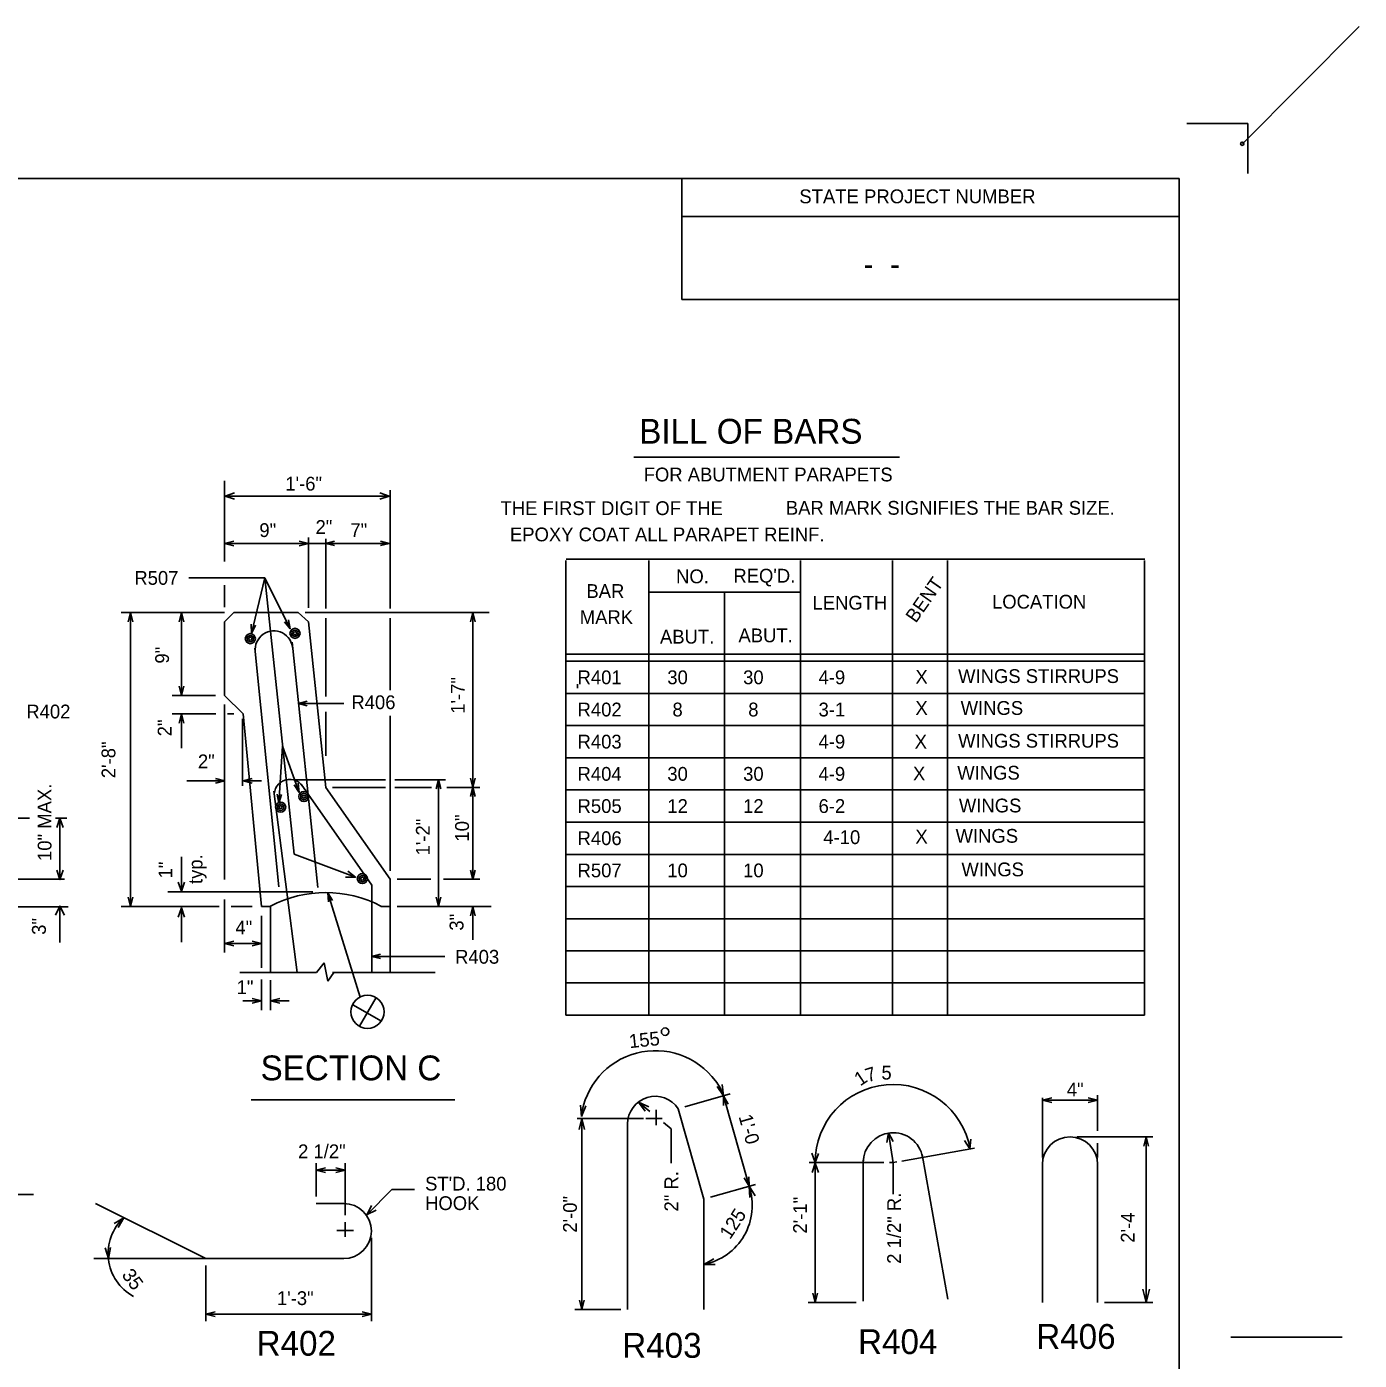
# Model space of a CAD drawing. Extents: x -3.6 to 32.6, y 15.5 to 40.2.
# Drawn here: x 20.52 to 32.6, y 27.56 to 39.65 of the extents above; entities that cross this region are included whole.
import ezdxf

# ---------------------------------------------------------------- set-up
doc = ezdxf.new("R2010")
doc.units = 0
for name, color, linetype in [('Level 1', 7, 'Continuous'), ('Level 2', 7, 'Continuous'), ('Level 37', 7, 'Continuous'), ('Level 49', 7, 'Continuous')]:
    doc.layers.add(name, color=color, linetype=linetype)

msp = doc.modelspace()

# ---------------------------------------------------------------- linework, layer by layer
at = {"layer": 'Level 1'}
for p, q in [((31.591, 38.772), (31.036, 38.772)), ((31.591, 38.317), (31.591, 38.772)), ((30.966, 38.272), (-0.41, 38.272)), ((26.46, 38.272), (26.46, 37.177)), ((30.966, 17.273), (30.966, 38.272)), ((26.46, 37.928), (30.966, 37.928)), ((26.46, 37.177), (30.966, 37.177))]:
    msp.add_line(p, q, dxfattribs=at)
at = {"layer": 'Level 2'}
for p, q in [((31.54, 38.588), (32.6, 39.649)), ((26.025, 35.748), (28.432, 35.748)), ((22.316, 35.006), (22.316, 35.532)), ((23.816, 35.018), (23.816, 35.447)), ((23.806, 35.394), (22.322, 35.394)), ((22.316, 35.006), (22.316, 34.802)), ((22.316, 34.965), (23.137, 34.965)), ((23.075, 34.381), (23.075, 35.018)), ((23.075, 34.687), (23.075, 34.965)), ((23.137, 34.965), (23.243, 34.965)), ((23.233, 34.375), (23.233, 35.006)), ((23.233, 34.965), (23.313, 34.985)), ((23.233, 34.965), (23.808, 34.965)), ((23.233, 34.965), (23.313, 34.945)), ((23.808, 34.965), (23.728, 34.985)), ((23.808, 34.965), (23.728, 34.945)), ((23.816, 34.375), (23.816, 35.018)), ((25.412, 34.822), (30.655, 34.822)), ((25.41, 34.81), (25.41, 30.689)), ((26.16, 34.81), (26.16, 30.689)), ((27.535, 34.81), (27.535, 30.689)), ((28.368, 34.81), (28.368, 30.689)), ((28.868, 34.81), (28.868, 30.689)), ((30.654, 34.81), (30.654, 30.689)), ((22.449, 34.653), (21.993, 34.653)), ((22.316, 34.387), (22.316, 34.586)), ((22.68, 34.653), (22.368, 34.653)), ((22.559, 34.15), (22.68, 34.653)), ((22.68, 34.653), (22.911, 34.19)), ((22.68, 34.653), (22.946, 32.149)), ((26.16, 34.522), (27.535, 34.522)), ((26.848, 34.522), (26.848, 30.689)), ((30.654, 34.522), (30.654, 30.689)), ((21.841, 34.338), (21.378, 34.338)), ((21.462, 31.674), (21.462, 34.338)), ((22.316, 34.338), (21.841, 34.338)), ((21.924, 33.588), (21.924, 34.338)), ((22.316, 34.254), (22.4, 34.338)), ((22.983, 34.338), (22.4, 34.338)), ((22.983, 34.338), (23.075, 34.255)), ((23.045, 34.338), (24.714, 34.338)), ((24.567, 32.754), (24.567, 34.338)), ((22.316, 34.254), (22.316, 33.588)), ((22.559, 34.15), (22.558, 34.232)), ((22.559, 34.15), (22.597, 34.223)), ((22.911, 34.19), (22.858, 34.253)), ((22.911, 34.19), (22.894, 34.271)), ((23.233, 32.754), (23.075, 34.255)), ((23.233, 33.577), (23.233, 34.289)), ((23.816, 33.635), (23.816, 34.289)), ((22.807, 31.853), (22.591, 34.016)), ((22.807, 31.853), (22.591, 34.016)), ((22.927, 34.07), (23.161, 31.847)), ((25.41, 33.96), (30.654, 33.96)), ((25.41, 33.897), (30.654, 33.897)), ((21.924, 33.755), (21.924, 33.588)), ((25.41, 33.606), (30.654, 33.606)), ((25.515, 33.689), (25.515, 33.654)), ((22.233, 33.588), (21.841, 33.588)), ((22.15, 33.588), (21.841, 33.588)), ((22.316, 33.588), (22.483, 33.421)), ((22.316, 33.504), (22.316, 31.919)), ((22.985, 33.514), (23.065, 33.534)), ((22.985, 33.514), (23.398, 33.514)), ((22.985, 33.514), (23.065, 33.494)), ((22.235, 33.421), (21.841, 33.421)), ((21.924, 33.11), (21.924, 33.421)), ((22.4, 33.421), (22.342, 33.421)), ((22.478, 33.374), (22.478, 32.767)), ((22.483, 33.421), (22.65, 31.674)), ((23.233, 33.039), (23.233, 33.438)), ((23.816, 31.998), (23.816, 33.403)), ((25.41, 33.314), (30.654, 33.314)), ((22.842, 33.126), (22.807, 32.611)), ((22.842, 33.126), (22.992, 32.709)), ((25.41, 33.022), (30.654, 33.022)), ((21.974, 32.814), (22.316, 32.814)), ((22.651, 32.814), (22.483, 32.814)), ((22.941, 32.823), (23.774, 32.823)), ((22.992, 32.709), (22.946, 32.778)), ((22.992, 32.709), (22.984, 32.791)), ((23.65, 31.868), (23.009, 32.784)), ((23.86, 32.823), (24.317, 32.823)), ((24.255, 31.674), (24.255, 32.823)), ((22.762, 32.72), (22.975, 31.076)), ((22.807, 32.611), (22.793, 32.692)), ((22.807, 32.611), (22.833, 32.689)), ((23.816, 31.921), (23.233, 32.754)), ((23.295, 32.754), (23.774, 32.754)), ((23.86, 32.754), (24.19, 32.754)), ((24.329, 32.754), (24.63, 32.754)), ((24.567, 31.921), (24.567, 32.754)), ((25.41, 32.731), (30.654, 32.731)), ((20.308, 32.474), (20.547, 32.474)), ((20.885, 32.474), (20.784, 32.474)), ((20.823, 32.474), (20.823, 31.919)), ((25.41, 32.439), (30.654, 32.439)), ((21.924, 32.123), (21.924, 31.812)), ((22.946, 32.149), (23.501, 31.939)), ((24.567, 32.089), (24.567, 31.921)), ((25.41, 32.147), (30.654, 32.147)), ((20.303, 31.921), (20.866, 31.921)), ((23.816, 31.921), (23.816, 31.076)), ((23.879, 31.921), (24.184, 31.921)), ((24.3, 31.921), (24.63, 31.921)), ((24.362, 31.921), (24.63, 31.921)), ((23.116, 31.806), (21.8, 31.806)), ((23.253, 31.799), (23.544, 30.853)), ((23.253, 31.799), (23.295, 31.728)), ((23.253, 31.799), (23.257, 31.716)), ((23.65, 31.868), (23.65, 31.076)), ((25.41, 31.856), (30.654, 31.856)), ((20.421, 31.671), (20.567, 31.671)), ((20.471, 31.671), (20.898, 31.671)), ((20.823, 31.671), (20.823, 31.347)), ((22.267, 31.674), (21.378, 31.674)), ((22.316, 31.257), (22.316, 31.737)), ((22.566, 31.674), (22.374, 31.674)), ((22.65, 31.674), (22.733, 31.674)), ((22.733, 31.674), (22.733, 31.076)), ((23.816, 31.674), (23.733, 31.674)), ((23.879, 31.674), (24.38, 31.674)), ((24.38, 31.674), (24.731, 31.674)), ((24.567, 31.373), (24.567, 31.674)), ((21.924, 31.35), (21.924, 31.661)), ((22.65, 31.591), (22.65, 31.174)), ((25.41, 31.564), (30.654, 31.564)), ((22.65, 31.34), (22.316, 31.34)), ((23.65, 31.222), (23.73, 31.242)), ((23.65, 31.222), (24.312, 31.222)), ((23.65, 31.222), (23.73, 31.202)), ((25.41, 31.272), (30.654, 31.272)), ((22.455, 31.076), (23.149, 31.076)), ((22.65, 31.174), (22.65, 31.118)), ((23.149, 31.076), (23.218, 31.164)), ((23.218, 31.164), (23.253, 30.997)), ((23.253, 30.997), (23.305, 31.076)), ((23.293, 31.076), (24.225, 31.076)), ((22.65, 31.014), (22.65, 30.736)), ((22.733, 31.008), (22.733, 30.736)), ((25.41, 30.981), (30.654, 30.981)), ((23.539, 30.591), (23.689, 30.85)), ((22.482, 30.82), (22.65, 30.82)), ((22.901, 30.82), (22.733, 30.82)), ((23.479, 30.784), (23.737, 30.635)), ((25.41, 30.689), (30.654, 30.689)), ((26.452, 30.689), (26.848, 30.689)), ((26.837, 29.958), (26.779, 30.043)), ((26.837, 29.958), (26.826, 30.06)), ((22.558, 29.921), (24.403, 29.921)), ((25.55, 29.772), (25.542, 29.875)), ((25.55, 29.772), (25.591, 29.867)), ((26.067, 29.902), (26.171, 29.816)), ((26.067, 29.902), (26.16, 29.858)), ((26.067, 29.902), (26.128, 29.819)), ((26.487, 29.859), (26.897, 29.975)), ((26.837, 29.958), (27.069, 29.139)), ((29.728, 29.398), (29.728, 29.94)), ((29.728, 29.919), (30.228, 29.919)), ((30.228, 29.963), (30.228, 29.641)), ((26.112, 29.752), (25.511, 29.752)), ((25.553, 29.752), (25.528, 29.652)), ((25.553, 29.752), (25.553, 28.022)), ((25.553, 29.752), (25.578, 29.652)), ((26.134, 29.752), (26.283, 29.752)), ((26.228, 29.832), (26.228, 29.691)), ((26.427, 29.841), (26.659, 29.022)), ((25.968, 28.022), (25.968, 29.704)), ((26.293, 29.716), (26.362, 29.658)), ((26.362, 29.658), (26.362, 29.349)), ((28.334, 29.623), (28.375, 29.352)), ((30.041, 29.586), (30.73, 29.586)), ((30.228, 29.398), (30.228, 29.529)), ((30.668, 29.586), (30.668, 28.086)), ((28.103, 28.096), (28.103, 29.374)), ((29.112, 29.484), (28.455, 29.367)), ((28.637, 29.427), (28.871, 28.114)), ((23.146, 29.045), (23.146, 29.347)), ((23.409, 29.285), (23.146, 29.285)), ((23.409, 28.876), (23.409, 29.347)), ((28.291, 29.353), (27.614, 29.353)), ((27.667, 29.339), (27.667, 28.086)), ((28.374, 29.353), (28.341, 29.353)), ((28.409, 29.359), (28.374, 29.353)), ((28.375, 29.352), (28.375, 29.067)), ((29.728, 28.086), (29.728, 29.336)), ((30.228, 29.336), (30.228, 28.086)), ((26.719, 29.039), (27.129, 29.156)), ((27.069, 29.139), (27.124, 29.051)), ((27.069, 29.139), (27.076, 29.036)), ((20.058, 29.063), (20.583, 29.063)), ((23.609, 28.882), (23.832, 29.11)), ((23.832, 29.11), (24.036, 29.11)), ((26.659, 29.022), (26.659, 28.022)), ((22.146, 28.483), (21.146, 28.983)), ((23.396, 28.983), (23.146, 28.983)), ((21.403, 28.854), (21.315, 28.801)), ((21.403, 28.854), (21.35, 28.766)), ((23.409, 28.681), (23.409, 28.814)), ((23.483, 28.739), (23.334, 28.739)), ((23.646, 28.67), (23.646, 27.917)), ((21.263, 28.483), (21.233, 28.581)), ((21.263, 28.483), (21.282, 28.584)), ((22.146, 28.483), (21.131, 28.483)), ((22.146, 28.483), (23.396, 28.483)), ((22.146, 28.42), (22.146, 27.917)), ((26.659, 28.431), (26.75, 28.48)), ((26.659, 28.431), (26.762, 28.431)), ((30.668, 28.086), (30.638, 28.206)), ((30.668, 28.086), (30.698, 28.206)), ((28.039, 28.086), (27.605, 28.086)), ((30.291, 28.086), (30.73, 28.086)), ((23.646, 27.979), (22.146, 27.979)), ((25.906, 28.022), (25.49, 28.022))]:
    msp.add_line(p, q, dxfattribs=at)
for points in [[(22.406, 35.423), (22.322, 35.394), (22.406, 35.365)], [(23.722, 35.365), (23.806, 35.394), (23.722, 35.423)], [(23.722, 35.365), (23.806, 35.394), (23.722, 35.423)], [(22.4, 34.986), (22.316, 34.965), (22.4, 34.944)], [(22.991, 34.986), (23.075, 34.965), (22.991, 34.944)], [(21.441, 34.254), (21.462, 34.338), (21.483, 34.254)], [(21.904, 34.254), (21.924, 34.338), (21.945, 34.254)], [(24.546, 34.254), (24.567, 34.338), (24.588, 34.254)], [(21.904, 33.671), (21.924, 33.588), (21.945, 33.671)], [(21.945, 33.671), (21.924, 33.588), (21.904, 33.671)], [(21.945, 33.337), (21.924, 33.421), (21.904, 33.337)], [(22.232, 32.835), (22.316, 32.814), (22.232, 32.793)], [(22.567, 32.835), (22.483, 32.814), (22.567, 32.793)], [(24.234, 32.74), (24.255, 32.823), (24.276, 32.74)], [(24.546, 32.838), (24.567, 32.754), (24.588, 32.838)], [(24.546, 32.67), (24.567, 32.754), (24.588, 32.67)], [(20.852, 32.389), (20.823, 32.474), (20.794, 32.389)], [(20.852, 32.389), (20.823, 32.474), (20.794, 32.389)], [(20.794, 32.004), (20.823, 31.919), (20.852, 32.004)], [(23.411, 31.941), (23.501, 31.939), (23.432, 31.996)], [(24.546, 32.005), (24.567, 31.921), (24.588, 32.005)], [(24.588, 32.005), (24.567, 31.921), (24.546, 32.005)], [(21.954, 31.896), (21.924, 31.812), (21.895, 31.896)], [(20.865, 31.595), (20.823, 31.678), (20.782, 31.595)], [(21.441, 31.758), (21.462, 31.674), (21.483, 31.758)], [(24.234, 31.758), (24.255, 31.674), (24.276, 31.758)], [(24.588, 31.59), (24.567, 31.674), (24.546, 31.59)], [(21.895, 31.577), (21.924, 31.661), (21.954, 31.577)], [(22.4, 31.319), (22.316, 31.34), (22.4, 31.361)], [(22.566, 31.319), (22.65, 31.34), (22.566, 31.361)], [(22.566, 30.841), (22.65, 30.82), (22.566, 30.799)], [(22.817, 30.841), (22.733, 30.82), (22.817, 30.799)], [(26.88, 29.883), (26.837, 29.958), (26.839, 29.871)], [(29.812, 29.941), (29.728, 29.92), (29.812, 29.899)], [(30.144, 29.941), (30.228, 29.92), (30.144, 29.899)], [(28.318, 29.535), (28.334, 29.623), (28.375, 29.544)], [(29.08, 29.566), (29.071, 29.477), (29.023, 29.553)], [(29.08, 29.566), (29.071, 29.477), (29.023, 29.553)], [(30.689, 29.502), (30.668, 29.586), (30.647, 29.502)], [(27.698, 29.437), (27.667, 29.353), (27.639, 29.438)], [(23.23, 29.306), (23.146, 29.285), (23.23, 29.264)], [(23.325, 29.306), (23.409, 29.285), (23.325, 29.264)], [(27.64, 29.264), (27.669, 29.349), (27.698, 29.264)], [(27.066, 29.225), (27.069, 29.139), (27.026, 29.214)], [(23.647, 28.963), (23.609, 28.882), (23.689, 28.922)], [(27.688, 28.17), (27.667, 28.086), (27.646, 28.17)], [(25.574, 28.106), (25.553, 28.022), (25.532, 28.106)], [(22.23, 28), (22.146, 27.979), (22.23, 27.958)], [(23.563, 28), (23.646, 27.979), (23.563, 27.958)]]:
    msp.add_lwpolyline(points, dxfattribs=at)
for centre, radius in [((22.549, 34.102), 0.0456), ((22.549, 34.102), 0.0292), ((22.549, 34.102), 0.0136), ((22.954, 34.15), 0.0456), ((22.954, 34.15), 0.0292), ((22.954, 34.15), 0.0136), ((23.035, 32.671), 0.0456), ((23.035, 32.671), 0.0292), ((23.035, 32.671), 0.0136), ((22.824, 32.575), 0.0456), ((22.824, 32.575), 0.0292), ((22.824, 32.575), 0.0136), ((23.564, 31.927), 0.0456), ((23.564, 31.927), 0.0292), ((23.564, 31.927), 0.0136), ((23.611, 30.72), 0.15), ((26.308, 30.54), 0.0337)]:
    msp.add_circle(centre, radius, dxfattribs=at)
for centre, radius, start, end in [((22.763, 34.002), 0.17, 1.4058, 186.5493), ((22.763, 34.002), 0.17, 1.4058, 186.5493), ((22.906, 32.686), 0.14, 33.7212, 196.604), ((23.233, 30.708), 1.092, 62.7558, 117.2442), ((26.221, 29.692), 0.676, 36.5307, 173.16), ((26.441, 29.835), 0.414, 17.2823, 38.7279), ((28.375, 29.353), 0.708, 10.1151, 180.0035), ((26.218, 29.704), 0.25, 33.4695, 180), ((26.221, 29.692), 0.676, 179.9929, 180), ((28.375, 29.353), 0.271, 10.1151, 180.0035), ((29.978, 29.336), 0.25, 90, 180), ((29.978, 29.336), 0.25, 360, 90), ((26.556, 28.963), 0.542, 280.9471, 18.8779), ((23.396, 28.733), 0.25, 0, 90), ((21.704, 28.529), 0.444, 132.7348, 241.0379), ((23.396, 28.733), 0.25, 270, 0)]:
    msp.add_arc(centre, radius, start, end, dxfattribs=at)
at = {"layer": 'Level 37'}
msp.add_line((31.436, 27.772), (32.446, 27.772), dxfattribs=at)
at = {"layer": 'Level 49'}
msp.add_circle((31.539, 38.588), 0.0152, dxfattribs=at)

# ---------------------------------------------------------------- texts
at = {"layer": 'Level 1'}
for s, height, p in [('STATE PROJECT NUMBER', 0.12525, (27.525, 38.048)), ('    -  -  ', 0.2023, (27.806, 37.396))]:
    msp.add_text(s, height=height, dxfattribs=at).set_placement(p)
at = {"layer": 'Level 2'}
for s, height, p in [('BILL OF BARS', 0.225, (26.074, 35.869)), ('1\'-6"', 0.125, (22.866, 35.444)), ('FOR ABUTMENT PARAPETS', 0.125, (26.114, 35.527)), (' THE FIRST DIGIT OF THE', 0.125, (24.771, 35.222)), ('BAR MARK SIGNIFIES THE BAR SIZE.', 0.125, (27.403, 35.225)), ('2"', 0.125, (23.14, 35.051)), ('9"', 0.125, (22.631, 35.023)), ('7"', 0.125, (23.456, 35.023)), ('EPOXY COAT ALL PARAPET REINF.', 0.125, (24.902, 34.984)), ('R507', 0.125, (21.498, 34.59)), ('NO.', 0.125, (26.408, 34.604)), ("REQ'D.", 0.125, (26.927, 34.61)), ('BAR', 0.125, (25.595, 34.471)), ('LENGTH', 0.125, (27.644, 34.365)), ('LOCATION', 0.125, (29.271, 34.374)), ('MARK', 0.125, (25.535, 34.234)), ('ABUT.', 0.125, (26.262, 34.057)), ('ABUT.', 0.125, (26.973, 34.069)), ('R401 ', 0.125, (25.515, 33.689)), (' 30 ', 0.125, (26.282, 33.689)), (' 30 ', 0.125, (26.969, 33.689)), ('  4-9 ', 0.125, (27.606, 33.689)), ('X', 0.125, (28.577, 33.693)), ('WINGS STIRRUPS', 0.125, (28.964, 33.7)), ('R402', 0.125, (20.519, 33.379)), ('R406', 0.125, (23.465, 33.463)), ('R402 ', 0.125, (25.515, 33.397)), ('  8 ', 0.125, (26.282, 33.397)), ('  8 ', 0.125, (26.969, 33.397)), ('  3-1 ', 0.125, (27.606, 33.397)), ('X', 0.125, (28.577, 33.411)), ('WINGS', 0.125, (28.987, 33.411)), ('WINGS STIRRUPS', 0.125, (28.964, 33.114)), ('R403 ', 0.125, (25.515, 33.106)), ('  4-9 ', 0.125, (27.606, 33.106)), ('X', 0.125, (28.57, 33.106)), ('2"', 0.125, (22.074, 32.927)), ('R404 ', 0.125, (25.515, 32.814)), (' 30 ', 0.125, (26.282, 32.814)), (' 30 ', 0.125, (26.969, 32.814)), ('  4-9 ', 0.125, (27.606, 32.814)), ('X', 0.125, (28.555, 32.817)), ('WINGS', 0.125, (28.956, 32.824)), ('R505 ', 0.125, (25.515, 32.522)), (' 12 ', 0.125, (26.282, 32.522)), (' 12 ', 0.125, (26.969, 32.522)), ('  6-2 ', 0.125, (27.606, 32.522)), ('WINGS', 0.125, (28.971, 32.527)), ('R406 ', 0.125, (25.515, 32.231)), (' 4-10 ', 0.125, (27.696, 32.24)), ('X', 0.125, (28.577, 32.245)), ('WINGS', 0.125, (28.941, 32.252)), ('R507 ', 0.125, (25.515, 31.939)), (' 10 ', 0.125, (26.282, 31.939)), (' 10 ', 0.125, (26.969, 31.939)), ('WINGS', 0.125, (28.994, 31.948)), ('4"', 0.125, (22.414, 31.422)), ('R403', 0.125, (24.405, 31.156)), ('1"', 0.125, (22.425, 30.88)), ('SECTION C', 0.225, (22.642, 30.099)), ('4"', 0.125, (29.949, 29.953)), ("ST'D. 180", 0.125, (24.133, 29.1)), ('HOOK', 0.125, (24.133, 28.923)), ('R402', 0.225, (22.606, 27.603)), ('R403', 0.225, (25.92, 27.584)), ('R404', 0.225, (28.057, 27.618)), ('R406', 0.225, (29.672, 27.665))]:
    msp.add_text(s, height=height, dxfattribs=at).set_placement(p)
for s, height, rotation, p in [('BENT', 0.125, 54.9952, (28.581, 34.237)), ('9"', 0.125, 90, (21.812, 33.876)), ('1\'-7"', 0.125, 90, (24.492, 33.421)), ('2"', 0.125, 90, (21.835, 33.217)), ('2\'-8"', 0.125, 90, (21.326, 32.837)), ('10" MAX.', 0.125, 90, (20.747, 32.087)), ('1\'-2"', 0.125, 90, (24.175, 32.137)), ('10"', 0.1258, 90, (24.531, 32.262)), ('1"', 0.125, 90, (21.842, 31.929)), ('typ.', 0.125, 90, (22.115, 31.878)), ('3"', 0.1258, 90, (20.696, 31.417)), ('3"', 0.1258, 90, (24.481, 31.455)), ('155', 0.125, 6, (25.988, 30.39)), ('7', 0.125, 17.9608, (28.146, 30.079)), ('5', 0.125, 359.0189, (28.268, 30.107)), ('1', 0.125, 34.0446, (28.076, 30.042)), ("1'-0", 0.125, 285.8272, (26.973, 29.771)), ('2 1/2"', 0.125, 360, (22.982, 29.393)), ('2" R.', 0.125, 90, (26.427, 28.91)), ('2\'-0"', 0.125, 90, (25.509, 28.718)), ('2\'-1"', 0.125, 90, (27.594, 28.71)), ('2 1/2" R.', 0.125, 90, (28.446, 28.436)), ('125', 0.125, 56.7478, (26.897, 28.65)), ("2'-4", 0.125, 90, (30.564, 28.627)), ('35', 0.125, 306.684, (21.378, 28.334)), ('1\'-3"', 0.125, 360, (22.79, 28.062))]:
    msp.add_text(s, height=height, rotation=rotation, dxfattribs=at).set_placement(p)

doc.saveas('drawing.dxf')
